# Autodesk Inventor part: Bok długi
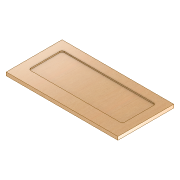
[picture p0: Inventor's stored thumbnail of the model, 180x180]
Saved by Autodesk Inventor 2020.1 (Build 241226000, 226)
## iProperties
Created: 2005-09
Part Number: Bok długi
Document SubType Name: Modeling
Designer: F.Stasiak
Density: 1 g/cm^3
Material: Ogólny
Appearance: Sosna żółta — pełna — barwiona na jasno — niski połysk
Manager: www.cadconsulting.pl
Company: Fabian Stasiak CAD Consulting
Author: F.Stasiak
Subject: Zbiór ćwiczeń. Autodesk Inventor 2020. Kurs podstawowy
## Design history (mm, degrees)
sketch "Szkic1"
  geometry: L1 (-250, 250)-(250, 250); L2 (250, 250)-(250, 0); L3 (250, 0)-(-250, 0); L4 (-250, 0)-(-250, 250); 2 further points
  constraints: 8 end point, 2 parallel, 1 coincident, 1 horizontal, 1 midpoint, 1 perpendicular
  dimensions: "d0" = 500 distance of L2.end L3.end; "d1" = 250 distance of L3.end L1.start
extrude "Wyciągnięcie proste1" new body sketch "Szkic1" distance "d2" = 15; taper "d3" = 0 deg
sketch "Szkic2"
  geometry: L1 (250, 250)-(250, 0) reference; L2 (-250, 250)-(250, 250) reference; L3 (-250, 0)-(-250, 250) reference; L4 (250, 0)-(-250, 0) reference; L5 (-210, 210)-(210, 210); L6 (210, 210)-(210, 60); L7 (210, 60)-(-210, 60); L8 (-210, 60)-(-210, 210)
  constraints: 8 end point, 2 parallel, 1 horizontal, 1 perpendicular
  dimensions: "d4" = 40 distance between parallel lines of L2 L5; "d5" = 60 distance between parallel lines of L4 L7; "d6" = 40 distance between parallel lines of L1 L6 (= d4); "d7" = 40 distance between parallel lines of L3 L8 (= d4)
extrude "Wyciągnięcie proste2" cut sketch "Szkic2" distance "d8" = 5; taper "d9" = 0 deg
fillet "Zaokrąglenie1" dims "d10" = 10
node "Bryła1"
node "Korpusy bryłowe"
node "Korpusy powierzchniowe"
node "Pętla rzutowana1"
